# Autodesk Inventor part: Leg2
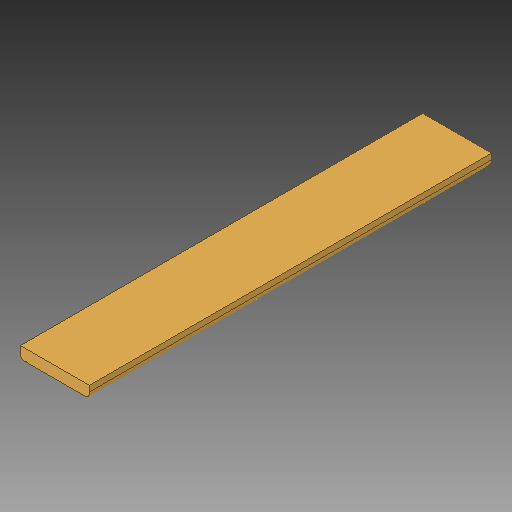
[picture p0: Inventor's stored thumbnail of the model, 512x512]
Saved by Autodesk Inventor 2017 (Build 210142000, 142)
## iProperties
Created: 2017-05
Part Number: Leg2
Material: Generic
Document SubType Name: Modeling
Designer: Savy
Density: 1 g/cm^3
Appearance: Default
Author: Savy
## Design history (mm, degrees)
feature "Base1"
body "Solid1"
